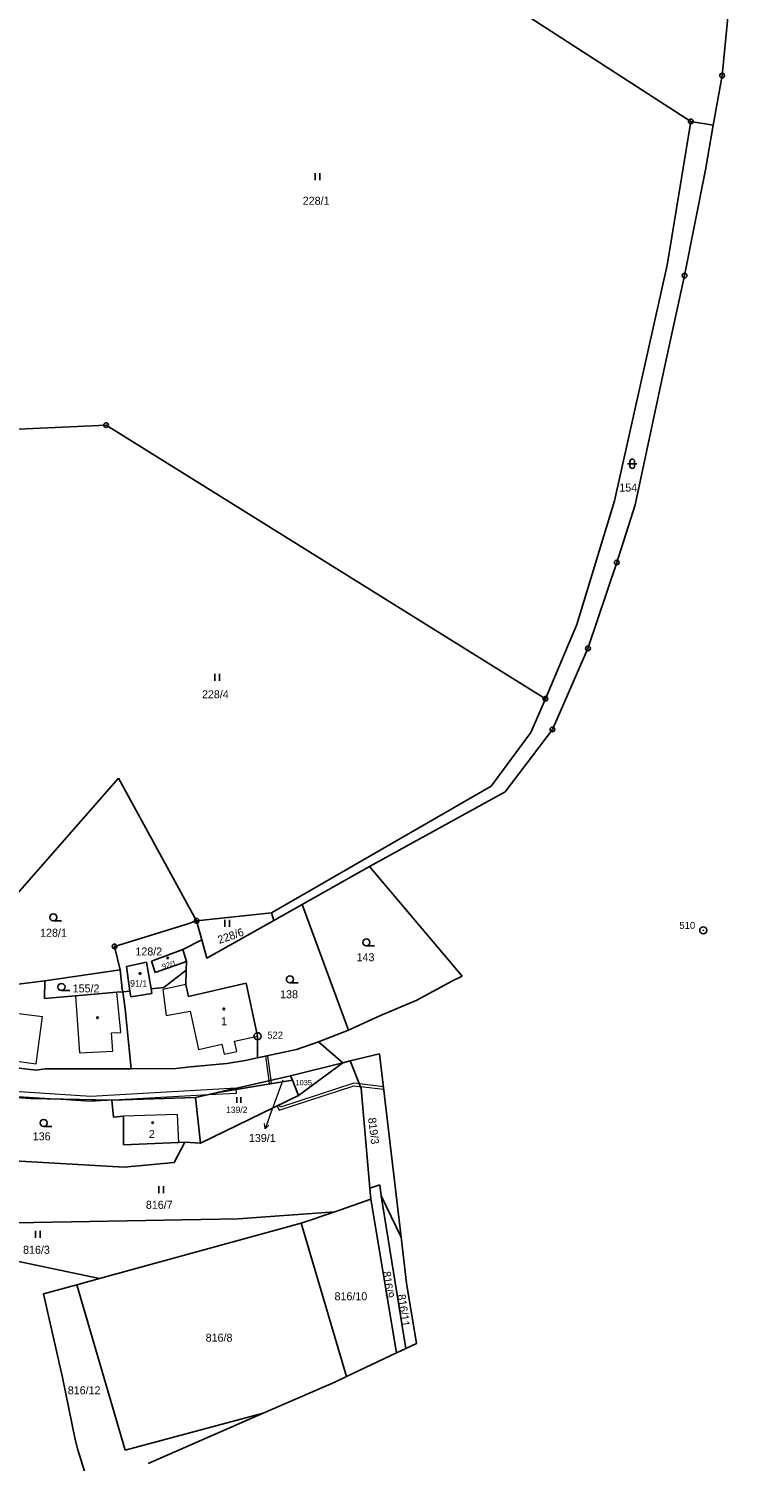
# Model space of a CAD drawing. Extents: x -754970 to -752637, y -970569 to -968179.
# Drawn here: x -752792.3 to -752643.2, y -969522.6 to -969218.4 of the extents above; entities that cross this region are included whole.
import ezdxf
from ezdxf.enums import TextEntityAlignment as Align

# ---------------------------------------------------------------- set-up
doc = ezdxf.new("R2010")
doc.units = 0
doc.header["$LTSCALE"] = 0.68
for name, color, linetype, lineweight in [('1', 7, 'Continuous', 25), ('13', 7, 'Continuous', 13), ('3', 7, 'Continuous', 25), ('4', 7, 'Continuous', 13), ('5', 7, 'Continuous', 25), ('7', 7, 'Continuous', 13), ('8', 7, 'Continuous', 25)]:
    doc.layers.add(name, color=color, linetype=linetype, lineweight=lineweight)
doc.layers.add('2', color=7, linetype='Continuous')

msp = doc.modelspace()

# ---------------------------------------------------------------- linework, layer by layer
at = {"layer": '1'}
for p, q in [((-752651.63, -969238.09), (-752726.91, -969189.49)), ((-752644.98, -969228.36), (-752643.23, -969210.72)), ((-752646.85, -969238.87), (-752644.98, -969228.36)), ((-752656.67, -969268.62), (-752651.63, -969238.09)), ((-752646.85, -969238.87), (-752651.63, -969238.09)), ((-752648.53, -969248.36), (-752646.85, -969238.87)), ((-752652.95, -969270.82), (-752648.53, -969248.36)), ((-752667.82, -969318.66), (-752656.67, -969268.62)), ((-752657.36, -969290.99), (-752652.95, -969270.82)), ((-752663.47, -969319.49), (-752657.36, -969290.99)), ((-752775.86, -969302.57), (-752803.85, -969303.87)), ((-752682.53, -969360.69), (-752775.86, -969302.57)), ((-752675.84, -969344.9), (-752667.82, -969318.66)), ((-752667.38, -969331.75), (-752663.47, -969319.49)), ((-752673.48, -969350.01), (-752667.38, -969331.75)), ((-752682.53, -969360.69), (-752675.84, -969344.9)), ((-752681.04, -969367.2), (-752673.48, -969350.01)), ((-752685.59, -969367.89), (-752682.53, -969360.69)), ((-752694.07, -969379.29), (-752685.59, -969367.89)), ((-752691.06, -969380.49), (-752681.04, -969367.2)), ((-752798.77, -969406.66), (-752773.21, -969377.55)), ((-752756.64, -969407.83), (-752773.21, -969377.55)), ((-752740.73, -969406.13), (-752694.07, -969379.29)), ((-752691.06, -969380.49), (-752719.92, -969396.35)), ((-752734.18, -969404.38), (-752719.92, -969396.35)), ((-752700.22, -969419.59), (-752719.92, -969396.35)), ((-752756.64, -969407.83), (-752740.73, -969406.13)), ((-752740.26, -969407.8), (-752740.73, -969406.13)), ((-752734.18, -969404.38), (-752740.26, -969407.8)), ((-752734.18, -969404.38), (-752724.39, -969431.06)), ((-752758.93, -969408.63), (-752774.06, -969413.28)), ((-752756.64, -969407.83), (-752758.93, -969408.63)), ((-752756.64, -969407.83), (-752755.51, -969411.92)), ((-752740.26, -969407.8), (-752754.45, -969415.78)), ((-752759.54, -969413.92), (-752755.51, -969411.92)), ((-752755.51, -969411.92), (-752754.45, -969415.78)), ((-752772.88, -969418.24), (-752774.06, -969413.28)), ((-752766.19, -969416.43), (-752759.54, -969413.92)), ((-752758.79, -969416.51), (-752759.54, -969413.92)), ((-752772.88, -969418.24), (-752788.87, -969420.63)), ((-752772.42, -969422.31), (-752772.88, -969418.24)), ((-752771.5, -969417.58), (-752767.25, -969416.66)), ((-752771.5, -969417.58), (-752770.79, -969422.76)), ((-752767.25, -969416.66), (-752766.31, -969422.31)), ((-752766.19, -969416.43), (-752765.47, -969418.86)), ((-752758.79, -969416.51), (-752765.47, -969418.86)), ((-752763.6, -969422.03), (-752758.83, -969418.36)), ((-752758.89, -969421.41), (-752758.83, -969418.36)), ((-752758.83, -969418.36), (-752758.79, -969416.51)), ((-752788.87, -969420.63), (-752805.01, -969422.57)), ((-752788.96, -969424.36), (-752788.87, -969420.63)), ((-752758.89, -969421.41), (-752758.34, -969423.95)), ((-752758.34, -969423.95), (-752746.07, -969421.11)), ((-752746.07, -969421.11), (-752743.69, -969432.35)), ((-752702.26, -969420.61), (-752709.81, -969424.68)), ((-752700.22, -969419.59), (-752702.26, -969420.61)), ((-752782.39, -969423.8), (-752788.96, -969424.36)), ((-752782.39, -969423.8), (-752773.59, -969423.03)), ((-752773.59, -969423.03), (-752772.33, -969422.92)), ((-752772.33, -969422.92), (-752772.42, -969422.31)), ((-752772.33, -969422.92), (-752770.79, -969422.76)), ((-752771.79, -969426.56), (-752772.33, -969422.92)), ((-752770.79, -969422.76), (-752770.62, -969424.03)), ((-752766.14, -969423.31), (-752770.62, -969424.03)), ((-752766.31, -969422.31), (-752763.6, -969422.03)), ((-752766.31, -969422.31), (-752766.14, -969423.31)), ((-752770.51, -969439.26), (-752771.79, -969426.56)), ((-752709.81, -969424.68), (-752717.54, -969427.93)), ((-752717.54, -969427.93), (-752724.39, -969431.06)), ((-752743.68, -969436.98), (-752743.69, -969432.35)), ((-752735.43, -969435.16), (-752730.77, -969433.56)), ((-752724.39, -969431.06), (-752730.77, -969433.56)), ((-752730.77, -969433.56), (-752725.6, -969438)), ((-752743.68, -969436.98), (-752735.43, -969435.16)), ((-752723.98, -969437.62), (-752717.79, -969436.08)), ((-752717.79, -969436.08), (-752713.18, -969475.05)), ((-752794.35, -969439.13), (-752790.7, -969439.55)), ((-752790.7, -969439.55), (-752788.78, -969439.32)), ((-752788.78, -969439.32), (-752770.51, -969439.26)), ((-752770.51, -969439.26), (-752760.97, -969439.21)), ((-752757.91, -969438.89), (-752760.97, -969439.21)), ((-752750.19, -969438.15), (-752757.91, -969438.89)), ((-752746.33, -969437.51), (-752750.19, -969438.15)), ((-752743.68, -969436.98), (-752746.33, -969437.51)), ((-752736.66, -969440.8), (-752725.6, -969438)), ((-752725.6, -969438), (-752734.98, -969444.94)), ((-752725.6, -969438), (-752723.98, -969437.62)), ((-752721.66, -969443.45), (-752723.98, -969437.62)), ((-752736.66, -969440.8), (-752736.29, -969441.71)), ((-752736.29, -969441.71), (-752734.98, -969444.94)), ((-752803.45, -969444.83), (-752791.94, -969445.58)), ((-752791.94, -969445.58), (-752774.65, -969445.96)), ((-752774.65, -969445.96), (-752756.87, -969445.39)), ((-752752.13, -969444.31), (-752756.87, -969445.39)), ((-752756.87, -969445.39), (-752755.78, -969455.09)), ((-752755.78, -969455.09), (-752734.98, -969444.94)), ((-752719.86, -969464.65), (-752721.66, -969443.45)), ((-752774.28, -969449.53), (-752774.65, -969445.96)), ((-752774.28, -969449.53), (-752772.2, -969449.34)), ((-752772.2, -969449.34), (-752772.19, -969455.45)), ((-752761.4, -969459.16), (-752759.14, -969454.83)), ((-752759.14, -969454.83), (-752760.47, -969454.94)), ((-752759.14, -969454.83), (-752755.78, -969455.09)), ((-752760.47, -969454.94), (-752772.19, -969455.45)), ((-752803.36, -969458.4), (-752772, -969460.14)), ((-752772, -969460.14), (-752761.4, -969459.16)), ((-752719.86, -969464.65), (-752717.72, -969463.94)), ((-752717.72, -969463.94), (-752717.45, -969466.23)), ((-752727.26, -969469.68), (-752719.64, -969466.97)), ((-752719.86, -969464.65), (-752719.64, -969466.97)), ((-752719.64, -969466.97), (-752714.14, -969499.6)), ((-752717.45, -969466.23), (-752712.19, -969498.68)), ((-752717.45, -969466.23), (-752713.18, -969475.05)), ((-752747.83, -969471.17), (-752727.26, -969469.68)), ((-752734.45, -969472.06), (-752727.26, -969469.68)), ((-752804.12, -969472.17), (-752747.83, -969471.17)), ((-752777.3, -969483.83), (-752734.45, -969472.06)), ((-752734.45, -969472.06), (-752724.8, -969504.63)), ((-752713.18, -969475.05), (-752712.02, -969484.81)), ((-752777.3, -969483.83), (-752796.46, -969479.74)), ((-752782.08, -969485.14), (-752789.16, -969487.09)), ((-752782.08, -969485.14), (-752777.3, -969483.83)), ((-752782.08, -969485.14), (-752771.81, -969520.24)), ((-752712.02, -969484.81), (-752709.93, -969497.61)), ((-752789.16, -969487.09), (-752785.15, -969504.82)), ((-752714.14, -969499.6), (-752724.8, -969504.63)), ((-752714.14, -969499.6), (-752712.19, -969498.68)), ((-752712.19, -969498.68), (-752709.93, -969497.61)), ((-752782.46, -969518.01), (-752785.15, -969504.82)), ((-752727.3, -969505.81), (-752742.52, -969512.44)), ((-752724.8, -969504.63), (-752727.3, -969505.81)), ((-752771.81, -969520.24), (-752742.52, -969512.44)), ((-752742.52, -969512.44), (-752766.94, -969523.07)), ((-752781.87, -969520.22), (-752782.46, -969518.01)), ((-752781.87, -969520.22), (-752779.48, -969527.88))]:
    msp.add_line(p, q, dxfattribs=at)
msp.add_lwpolyline([(-752736.29, -969441.71), (-752752.13, -969444.31), (-752736.66, -969440.8)], dxfattribs=at)
at = {"layer": '13'}
for points in [[(-752742, -969436.61), (-752741.29, -969441.85), (-752740.8, -969441.74), (-752741.51, -969436.5)], [(-752821.68, -969442.38), (-752819.87, -969442.54), (-752806.91, -969444.35), (-752795.65, -969445.1), (-752785.47, -969445.72), (-752775.64, -969445.94), (-752754.03, -969444.74), (-752748.22, -969443.42), (-752779.11, -969445.13), (-752807.38, -969443.31), (-752804.06, -969437.76), (-752805.11, -969437.56), (-752808.5, -969443.24), (-752821.76, -969442.11), (-752821.72, -969442.37)], [(-752741.29, -969441.85), (-752741.2, -969442.52), (-752740.7, -969442.43), (-752740.8, -969441.74)], [(-752739.09, -969446.94), (-752739.54, -969447.16), (-752739.1, -969448.03), (-752723.21, -969442.87), (-752721.83, -969443.03), (-752722.04, -969442.5), (-752723.26, -969442.36), (-752738.84, -969447.43)], [(-752721.83, -969443.03), (-752716.9, -969443.61), (-752716.96, -969443.1), (-752722.04, -969442.5)], [(-752785.47, -969445.72), (-752779.11, -969446.13), (-752776.05, -969445.96), (-752775.64, -969445.94)], [(-752748.16, -969444.42), (-752748.21, -969443.67), (-752748.22, -969443.42), (-752754.03, -969444.74)]]:
    msp.add_lwpolyline(points, close=True, dxfattribs=at)
at = {"layer": '3'}
for p, q in [((-752731.471, -969250.6), (-752731.471, -969249.1)), ((-752730.47, -969250.6), (-752730.47, -969249.1)), ((-752665.071, -969310.791), (-752663.069, -969310.791)), ((-752664.571, -969310.291), (-752664.571, -969311.292)), ((-752663.569, -969311.292), (-752663.569, -969310.291)), ((-752752.741, -969356.89), (-752752.741, -969355.39)), ((-752751.74, -969356.89), (-752751.74, -969355.39)), ((-752787.073, -969407.87), (-752785.323, -969407.87)), ((-752750.621, -969409.13), (-752750.621, -969407.63)), ((-752749.62, -969409.13), (-752749.62, -969407.63)), ((-752720.563, -969413.18), (-752718.813, -969413.18)), ((-752736.813, -969421.04), (-752735.063, -969421.04)), ((-752785.343, -969422.64), (-752783.593, -969422.64)), ((-752748.059, -969446.47), (-752748.059, -969445.27)), ((-752747.258, -969446.47), (-752747.258, -969445.27)), ((-752789.133, -969451.53), (-752787.383, -969451.53)), ((-752764.681, -969465.68), (-752764.681, -969464.18)), ((-752763.68, -969465.68), (-752763.68, -969464.18)), ((-752790.891, -969475.17), (-752790.891, -969473.67)), ((-752789.89, -969475.17), (-752789.89, -969473.67))]:
    msp.add_line(p, q, dxfattribs=at)
for centre in [(-752787.0729, -969407.1198), (-752720.5629, -969412.4298), (-752785.3429, -969421.8898), (-752736.8129, -969420.2898), (-752789.1329, -969450.7798)]:
    msp.add_circle(centre, 0.75, dxfattribs=at)
for centre, start, end in [((-752664.07, -969310.2909), 0, 180), ((-752664.07, -969311.2909), 180, 359.98789)]:
    msp.add_arc(centre, 0.5, start, end, dxfattribs=at)
at = {"layer": '4'}
for p, q in [((-752782.39, -969423.8), (-752781.52, -969435.86)), ((-752802.04, -969426.55), (-752789.39, -969428.18)), ((-752790.69, -969438.22), (-752789.39, -969428.18)), ((-752774.43, -969435.52), (-752774.72, -969431.62)), ((-752748.57, -969433.43), (-752743.69, -969432.35)), ((-752748.11, -969435.57), (-752748.57, -969433.43)), ((-752803.42, -969436.53), (-752790.69, -969438.22)), ((-752781.52, -969435.86), (-752774.43, -969435.52)), ((-752756.26, -969435.18), (-752751.29, -969434.03)), ((-752751.29, -969434.03), (-752750.79, -969436.19)), ((-752750.79, -969436.19), (-752748.11, -969435.57)), ((-752760.74, -969448.95), (-752772.2, -969449.34)), ((-752760.74, -969448.95), (-752760.47, -969454.94))]:
    msp.add_line(p, q, dxfattribs=at)
for points in [[(-752758.89, -969421.41), (-752763.82, -969422.44), (-752763.13, -969427.99), (-752758.01, -969427.06), (-752756.26, -969435.18)], [(-752774.72, -969431.62), (-752772.76, -969431.54), (-752773.59, -969423.03)]]:
    msp.add_lwpolyline(points, dxfattribs=at)
at = {"layer": '5'}
for centre in [(-752762.7668, -969415.7492), (-752768.6268, -969419.0392), (-752750.8468, -969426.5492), (-752777.6868, -969428.4192), (-752765.9768, -969450.7292)]:
    msp.add_circle(centre, 0.175, dxfattribs=at)
at = {"layer": '7'}
msp.add_line((-752742.086, -969452), (-752741.273, -969451.23), dxfattribs=at)
msp.add_lwpolyline([(-752738.31, -969441.69), (-752741.06, -969449.18), (-752742.086, -969452), (-752742.214, -969450.888)], dxfattribs=at)
at = {"layer": '8'}
for centre, radius in [((-752644.98, -969228.3599), 0.5), ((-752644.98, -969228.3599), 0.0303), ((-752651.63, -969238.0899), 0.5), ((-752651.63, -969238.0899), 0.0303), ((-752652.95, -969270.8199), 0.5), ((-752652.95, -969270.8199), 0.0303), ((-752775.86, -969302.5699), 0.5), ((-752775.86, -969302.5699), 0.0303), ((-752667.38, -969331.7499), 0.5), ((-752667.38, -969331.7499), 0.0303), ((-752673.48, -969350.0099), 0.5), ((-752673.48, -969350.0099), 0.0303), ((-752682.53, -969360.6899), 0.5), ((-752682.53, -969360.6899), 0.0303), ((-752681.04, -969367.1999), 0.5), ((-752681.04, -969367.1999), 0.0303), ((-752756.64, -969407.8299), 0.5), ((-752756.64, -969407.8299), 0.0303), ((-752648.99, -969409.8798), 0.75), ((-752648.99, -969409.8798), 0.03), ((-752774.06, -969413.2799), 0.5), ((-752774.06, -969413.2799), 0.0303), ((-752743.69, -969432.3598), 0.75), ((-752743.69, -969432.3598), 0.03)]:
    msp.add_circle(centre, radius, dxfattribs=at)

# ---------------------------------------------------------------- texts
at = {"layer": '2'}
for s, height, p in [('228/1', 1.7, (-752731.24, -969255.785)), ('154', 1.7, (-752664.929, -969316.705)), ('228/4', 1.7, (-752752.65, -969360.595)), ('128/1', 1.7, (-752787.04, -969411.235)), ('128/2', 1.7, (-752766.79, -969415.215)), ('143', 1.7, (-752720.749, -969416.435)), ('155/2', 1.7, (-752780.12, -969423.055)), ('91/1', 1.4, (-752768.949, -969421.86)), ('138', 1.7, (-752736.989, -969424.295)), ('1', 1.7, (-752750.8, -969430.025)), ('1035', 1.14, (-752733.869, -969442.785)), ('139/2', 1.354, (-752748.099, -969448.678)), ('136', 1.7, (-752789.549, -969454.465)), ('2', 1.7, (-752766.14, -969453.975)), ('139/1', 1.7, (-752742.67, -969454.825)), ('816/7', 1.7, (-752764.57, -969469.015)), ('816/3', 1.7, (-752790.66, -969478.565)), ('816/10', 1.7, (-752723.85, -969488.435)), ('816/8', 1.7, (-752751.87, -969497.225)), ('816/12', 1.7, (-752780.53, -969508.405))]:
    msp.add_text(s, height=height, dxfattribs=at).set_placement(p, align=Align.CENTER)
for s, height, rotation, p in [('228/6', 1.7, 19, (-752749.1207, -969411.8532)), ('92/1', 1.14, 16, (-752762.3311, -969417.7403)), ('819/3', 1.7, 277, (-752719.8649, -969452.5639)), ('816/9', 1.7, 278, (-752716.7218, -969485.2387)), ('816/11', 1.7, 278, (-752713.4721, -969490.6992))]:
    msp.add_text(s, height=height, rotation=rotation, dxfattribs=at).set_placement(p, align=Align.CENTER)
at = {"layer": '8'}
for s, p in [('510', (-752650.71, -969409.575)), ('522', (-752738.271, -969432.893))]:
    msp.add_text(s, height=1.5, dxfattribs=at).set_placement(p, align=Align.RIGHT)

doc.saveas('drawing.dxf')
